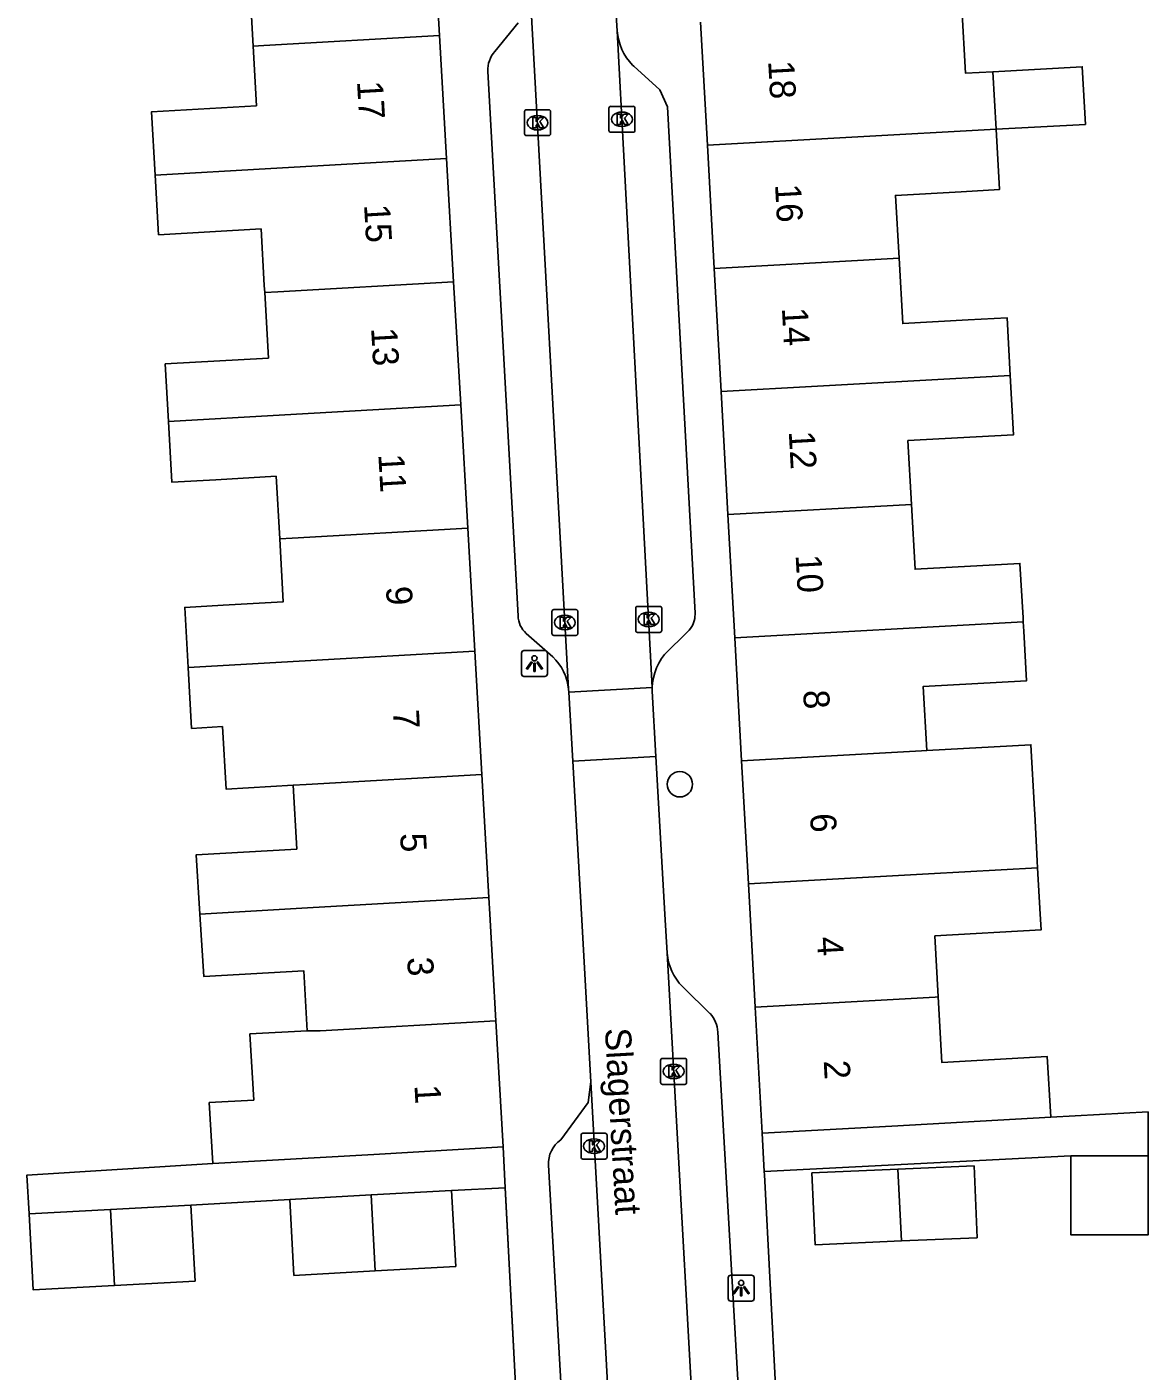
# Model space of a CAD drawing. Extents: x 160861 to 161308, y 384024 to 384878.
# Drawn here: x 161040 to 161083.2, y 384732.4 to 384784.2 of the extents above; entities that cross this region are included whole.
import ezdxf

# ---------------------------------------------------------------- set-up
doc = ezdxf.new("R2010")
doc.units = 0
for name, color, linetype in [('IMGEO_Boom', 7, 'Continuous'), ('IMGEO_Kolk', 7, 'Continuous'), ('IMGEO_Lichtpunt', 7, 'Continuous'), ('IMGEO_Muur', 7, 'Continuous'), ('IMGEO_Openbare_ruimte_label', 7, 'Continuous'), ('IMGEO_Pand', 7, 'Continuous'), ('IMGEO_Pand_nummerreeks', 7, 'Continuous'), ('IMGEO_Rijbaan_lokaal_open', 7, 'Continuous'), ('IMGEO_Voetpad_open', 7, 'Continuous')]:
    doc.layers.add(name, color=color, linetype=linetype)

msp = doc.modelspace()

# ---------------------------------------------------------------- linework, layer by layer
at = {"layer": 'IMGEO_Boom'}
msp.add_circle((161065.12, 384755.001), 0.489, dxfattribs=at)
at = {"layer": 'IMGEO_Kolk'}
for p, q in [((161059.133, 384780.08), (161059.133, 384780.932)), ((161059.208, 384781.006), (161060.06, 384781.006)), ((161059.621, 384780.786), (161059.646, 384780.786)), ((161060.134, 384780.932), (161060.134, 384780.08)), ((161062.387, 384780.21), (161062.387, 384781.062)), ((161062.462, 384781.136), (161063.314, 384781.136)), ((161062.875, 384780.916), (161062.9, 384780.916)), ((161063.388, 384781.062), (161063.388, 384780.21)), ((161059.644, 384780.226), (161059.619, 384780.226)), ((161062.898, 384780.356), (161062.873, 384780.356)), ((161060.06, 384780.006), (161059.208, 384780.006)), ((161063.314, 384780.136), (161062.462, 384780.136)), ((161060.187, 384760.812), (161060.187, 384761.664)), ((161060.262, 384761.738), (161061.114, 384761.738)), ((161060.675, 384761.518), (161060.7, 384761.518)), ((161061.188, 384761.664), (161061.188, 384760.812)), ((161063.417, 384760.932), (161063.417, 384761.784)), ((161063.492, 384761.858), (161064.344, 384761.858)), ((161063.905, 384761.638), (161063.93, 384761.638)), ((161064.418, 384761.784), (161064.418, 384760.932)), ((161063.928, 384761.078), (161063.903, 384761.078)), ((161061.114, 384760.738), (161060.262, 384760.738)), ((161060.698, 384760.958), (161060.673, 384760.958)), ((161064.344, 384760.858), (161063.492, 384760.858)), ((161064.453, 384744.433), (161065.305, 384744.433)), ((161064.378, 384743.507), (161064.378, 384744.359)), ((161064.866, 384744.213), (161064.891, 384744.213)), ((161065.379, 384744.359), (161065.379, 384743.507)), ((161065.305, 384743.433), (161064.453, 384743.433)), ((161064.889, 384743.653), (161064.864, 384743.653)), ((161061.31, 384740.624), (161061.31, 384741.476)), ((161061.385, 384741.55), (161062.237, 384741.55)), ((161061.798, 384741.33), (161061.823, 384741.33)), ((161062.311, 384741.476), (161062.311, 384740.624)), ((161062.237, 384740.55), (161061.385, 384740.55)), ((161061.821, 384740.77), (161061.796, 384740.77))]:
    msp.add_line(p, q, dxfattribs=at)
for points in [[(161059.133, 384780.08), (161059.133, 384780.932)], [(161059.208, 384781.006), (161060.06, 384781.006)], [(161059.454, 384780.706), (161059.577, 384780.706), (161059.577, 384780.555), (161059.707, 384780.706), (161059.871, 384780.706), (161059.725, 384780.555), (161059.878, 384780.306), (161059.726, 384780.306), (161059.641, 384780.47), (161059.577, 384780.403), (161059.577, 384780.306), (161059.454, 384780.306), (161059.454, 384780.706)], [(161060.134, 384780.932), (161060.134, 384780.08)], [(161062.387, 384780.21), (161062.387, 384781.062)], [(161062.462, 384781.136), (161063.314, 384781.136)], [(161062.708, 384780.836), (161062.831, 384780.836), (161062.831, 384780.685), (161062.961, 384780.836), (161063.125, 384780.836), (161062.979, 384780.685), (161063.132, 384780.436), (161062.98, 384780.436), (161062.895, 384780.6), (161062.831, 384780.533), (161062.831, 384780.436), (161062.708, 384780.436), (161062.708, 384780.836)], [(161063.388, 384781.062), (161063.388, 384780.21)], [(161060.06, 384780.006), (161059.208, 384780.006)], [(161063.314, 384780.136), (161062.462, 384780.136)], [(161060.187, 384760.812), (161060.187, 384761.664)], [(161060.262, 384761.738), (161061.114, 384761.738)], [(161061.188, 384761.664), (161061.188, 384760.812)], [(161063.417, 384760.932), (161063.417, 384761.784)], [(161063.492, 384761.858), (161064.344, 384761.858)], [(161063.738, 384761.558), (161063.861, 384761.558), (161063.861, 384761.407), (161063.991, 384761.558), (161064.155, 384761.558), (161064.009, 384761.407), (161064.162, 384761.158), (161064.01, 384761.158), (161063.925, 384761.322), (161063.861, 384761.255), (161063.861, 384761.158), (161063.738, 384761.158), (161063.738, 384761.558)], [(161064.418, 384761.784), (161064.418, 384760.932)], [(161060.508, 384761.438), (161060.631, 384761.438), (161060.631, 384761.287), (161060.761, 384761.438), (161060.925, 384761.438), (161060.779, 384761.287), (161060.932, 384761.038), (161060.78, 384761.038), (161060.695, 384761.202), (161060.631, 384761.135), (161060.631, 384761.038), (161060.508, 384761.038), (161060.508, 384761.438)], [(161061.114, 384760.738), (161060.262, 384760.738)], [(161064.344, 384760.858), (161063.492, 384760.858)], [(161064.453, 384744.433), (161065.305, 384744.433)], [(161064.378, 384743.507), (161064.378, 384744.359)], [(161064.699, 384744.133), (161064.822, 384744.133), (161064.822, 384743.982), (161064.952, 384744.133), (161065.116, 384744.133), (161064.97, 384743.982), (161065.123, 384743.733), (161064.971, 384743.733), (161064.886, 384743.897), (161064.822, 384743.83), (161064.822, 384743.733), (161064.699, 384743.733), (161064.699, 384744.133)], [(161065.379, 384744.359), (161065.379, 384743.507)], [(161065.305, 384743.433), (161064.453, 384743.433)], [(161061.31, 384740.624), (161061.31, 384741.476)], [(161061.385, 384741.55), (161062.237, 384741.55)], [(161062.311, 384741.476), (161062.311, 384740.624)], [(161061.631, 384741.25), (161061.754, 384741.25), (161061.754, 384741.099), (161061.884, 384741.25), (161062.048, 384741.25), (161061.902, 384741.099), (161062.055, 384740.85), (161061.903, 384740.85), (161061.818, 384741.014), (161061.754, 384740.947), (161061.754, 384740.85), (161061.631, 384740.85), (161061.631, 384741.25)], [(161062.237, 384740.55), (161061.385, 384740.55)]]:
    msp.add_lwpolyline(points, dxfattribs=at)
for centre, start, end in [((161059.21, 384780.93), 91.552, 178.448), ((161059.21, 384780.93), 91.552, 178.448), ((161060.058, 384780.93), 1.552, 88.448), ((161060.058, 384780.93), 1.552, 88.448), ((161062.464, 384781.06), 91.552, 178.448), ((161062.464, 384781.06), 91.552, 178.448), ((161063.312, 384781.06), 1.552, 88.448), ((161063.312, 384781.06), 1.552, 88.448), ((161062.464, 384780.212), 181.552, 268.448), ((161062.464, 384780.212), 181.552, 268.448), ((161063.312, 384780.212), 271.552, 358.448), ((161063.312, 384780.212), 271.552, 358.448), ((161059.21, 384780.082), 181.552, 268.448), ((161059.21, 384780.082), 181.552, 268.448), ((161060.058, 384780.082), 271.552, 358.448), ((161060.058, 384780.082), 271.552, 358.448), ((161060.264, 384761.662), 91.552, 178.448), ((161060.264, 384761.662), 91.552, 178.448), ((161061.112, 384761.662), 1.552, 88.448), ((161061.112, 384761.662), 1.552, 88.448), ((161063.494, 384761.782), 91.552, 178.448), ((161063.494, 384761.782), 91.552, 178.448), ((161064.342, 384761.782), 1.552, 88.448), ((161064.342, 384761.782), 1.552, 88.448), ((161060.264, 384760.814), 181.552, 268.448), ((161060.264, 384760.814), 181.552, 268.448), ((161061.112, 384760.814), 271.552, 358.448), ((161061.112, 384760.814), 271.552, 358.448), ((161063.494, 384760.934), 181.552, 268.448), ((161063.494, 384760.934), 181.552, 268.448), ((161064.342, 384760.934), 271.552, 358.448), ((161064.342, 384760.934), 271.552, 358.448), ((161064.455, 384744.357), 91.552, 178.448), ((161064.455, 384744.357), 91.552, 178.448), ((161065.303, 384744.357), 1.552, 88.448), ((161065.303, 384744.357), 1.552, 88.448), ((161064.455, 384743.509), 181.552, 268.448), ((161064.455, 384743.509), 181.552, 268.448), ((161065.303, 384743.509), 271.552, 358.448), ((161065.303, 384743.509), 271.552, 358.448), ((161061.387, 384741.474), 91.552, 178.448), ((161061.387, 384741.474), 91.552, 178.448), ((161062.235, 384741.474), 1.552, 88.448), ((161062.235, 384741.474), 1.552, 88.448), ((161061.387, 384740.626), 181.552, 268.448), ((161061.387, 384740.626), 181.552, 268.448), ((161062.235, 384740.626), 271.552, 358.448), ((161062.235, 384740.626), 271.552, 358.448)]:
    msp.add_arc(centre, 0.0765, start, end, dxfattribs=at)
for centre, major_axis, ratio, start_param, end_param in [((161059.62, 384780.506), (-0.387, 0.002), 0.722429, 4.712389, 7.853982), ((161059.645, 384780.506), (-0.39, 0.002), 0.717154, 1.570796, 4.712389), ((161062.874, 384780.636), (-0.387, 0.002), 0.722429, 4.712389, 7.853982), ((161062.899, 384780.636), (-0.39, 0.002), 0.717154, 1.570796, 4.712389), ((161060.674, 384761.238), (-0.387, 0.002), 0.722429, 4.712389, 7.853982), ((161060.699, 384761.238), (-0.39, 0.002), 0.717154, 1.570796, 4.712389), ((161063.904, 384761.358), (-0.387, 0.002), 0.722429, 4.712389, 7.853982), ((161063.929, 384761.358), (-0.39, 0.002), 0.717154, 1.570796, 4.712389), ((161064.865, 384743.933), (-0.387, 0.002), 0.722429, 4.712389, 7.853982), ((161064.89, 384743.933), (-0.39, 0.002), 0.717154, 1.570796, 4.712389), ((161061.797, 384741.05), (-0.387, 0.002), 0.722429, 4.712389, 7.853982), ((161061.822, 384741.05), (-0.39, 0.002), 0.717154, 1.570796, 4.712389)]:
    msp.add_ellipse(centre, major_axis=major_axis, ratio=ratio, start_param=start_param, end_param=end_param, dxfattribs=at)
at = {"layer": 'IMGEO_Lichtpunt'}
for p, q in [((161059.016, 384760.06), (161059.016, 384759.253)), ((161059.016, 384760.06), (161059.016, 384759.253)), ((161059.918, 384760.155), (161059.11, 384760.155)), ((161059.918, 384760.155), (161059.11, 384760.155)), ((161060.012, 384759.253), (161060.012, 384760.06)), ((161060.012, 384759.253), (161060.012, 384760.06)), ((161059.11, 384759.159), (161059.918, 384759.159)), ((161059.11, 384759.159), (161059.918, 384759.159)), ((161066.984, 384735.981), (161066.984, 384735.174)), ((161066.984, 384735.981), (161066.984, 384735.174)), ((161067.886, 384736.076), (161067.078, 384736.076)), ((161067.886, 384736.076), (161067.078, 384736.076)), ((161067.98, 384735.174), (161067.98, 384735.981)), ((161067.98, 384735.174), (161067.98, 384735.981)), ((161067.078, 384735.08), (161067.886, 384735.08)), ((161067.078, 384735.08), (161067.886, 384735.08))]:
    msp.add_line(p, q, dxfattribs=at)
for points in [[(161059.39, 384759.724), (161059.429, 384759.696), (161059.241, 384759.434), (161059.203, 384759.461), (161059.39, 384759.724)], [(161059.492, 384759.676), (161059.539, 384759.676), (161059.539, 384759.354), (161059.492, 384759.354), (161059.492, 384759.676)], [(161059.602, 384759.696), (161059.64, 384759.723), (161059.827, 384759.461), (161059.788, 384759.433), (161059.602, 384759.696)], [(161067.358, 384735.645), (161067.397, 384735.617), (161067.209, 384735.355), (161067.171, 384735.382), (161067.358, 384735.645)], [(161067.57, 384735.617), (161067.608, 384735.644), (161067.795, 384735.382), (161067.756, 384735.354), (161067.57, 384735.617)], [(161067.46, 384735.597), (161067.507, 384735.597), (161067.507, 384735.275), (161067.46, 384735.275), (161067.46, 384735.597)]]:
    msp.add_lwpolyline(points, dxfattribs=at)
for centre in [(161059.515, 384759.858), (161067.483, 384735.779)]:
    msp.add_circle(centre, 0.0994, dxfattribs=at)
for centre, start, end in [((161059.11, 384760.06), 90, 180), ((161059.11, 384760.06), 90, 180), ((161059.918, 384760.06), 0, 90), ((161059.918, 384760.06), 0, 90), ((161059.11, 384759.253), 180, 270), ((161059.11, 384759.253), 180, 270), ((161059.918, 384759.253), 270, 0), ((161059.918, 384759.253), 270, 360), ((161067.078, 384735.981), 90, 180), ((161067.078, 384735.981), 90, 180), ((161067.886, 384735.981), 0, 90), ((161067.886, 384735.981), 0, 90), ((161067.078, 384735.174), 180, 270), ((161067.078, 384735.174), 180, 270), ((161067.886, 384735.174), 270, 0), ((161067.886, 384735.174), 270, 360)]:
    msp.add_arc(centre, 0.0946, start, end, dxfattribs=at)
at = {"layer": 'IMGEO_Muur'}
for points in [[(161068.378, 384739.94), (161068.814, 384731.561)], [(161058.391, 384739.453), (161058.841, 384730.88)]]:
    msp.add_lwpolyline(points, dxfattribs=at)
at = {"layer": 'IMGEO_Pand'}
for points in [[(161055.585, 384788.618), (161055.857, 384783.87)], [(161048.67, 384783.459), (161048.538, 384785.766), (161044.542, 384785.537), (161044.402, 384787.978)], [(161073.083, 384784.777), (161075.991, 384784.939), (161076.132, 384782.412), (161077.185, 384782.47)], [(161066.178, 384779.633), (161065.914, 384784.379)], [(161055.857, 384783.87), (161049.083, 384783.483), (161048.67, 384783.459)], [(161055.857, 384783.87), (161056.129, 384779.122)], [(161044.896, 384778.48), (161044.756, 384780.929), (161048.801, 384781.161), (161048.67, 384783.459)], [(161077.309, 384780.251), (161080.753, 384780.441), (161080.631, 384782.66), (161077.185, 384782.47)], [(161077.185, 384782.47), (161077.309, 384780.251)], [(161077.309, 384780.251), (161066.178, 384779.633)], [(161077.309, 384780.251), (161077.438, 384777.926), (161075.957, 384777.843), (161073.43, 384777.701), (161073.566, 384775.283)], [(161066.442, 384774.887), (161066.178, 384779.633)], [(161056.129, 384779.122), (161049.355, 384778.735), (161044.896, 384778.48)], [(161056.129, 384779.122), (161056.4, 384774.374)], [(161049.117, 384773.958), (161049.102, 384774.223), (161048.976, 384776.411), (161045.027, 384776.185), (161044.896, 384778.48)], [(161066.442, 384774.887), (161073.566, 384775.283)], [(161073.566, 384775.283), (161073.707, 384772.761), (161076.232, 384772.901), (161077.732, 384772.984), (161077.856, 384770.761)], [(161066.705, 384770.141), (161066.442, 384774.887)], [(161045.408, 384768.982), (161045.281, 384771.204), (161049.263, 384771.434), (161049.117, 384773.958)], [(161056.4, 384774.374), (161049.627, 384773.987), (161049.117, 384773.958)], [(161056.4, 384774.374), (161056.672, 384769.627)], [(161066.705, 384770.141), (161077.856, 384770.761)], [(161077.856, 384770.761), (161077.983, 384768.478), (161073.91, 384768.252), (161074.047, 384765.789)], [(161066.969, 384765.395), (161066.705, 384770.141)], [(161045.408, 384768.982), (161049.899, 384769.239), (161056.672, 384769.627)], [(161056.672, 384769.627), (161056.944, 384764.879)], [(161049.695, 384764.464), (161049.558, 384766.875), (161047.24, 384766.743), (161045.541, 384766.646), (161045.408, 384768.982)], [(161074.047, 384765.789), (161066.969, 384765.395)], [(161074.047, 384765.789), (161074.186, 384763.289), (161078.225, 384763.513), (161078.345, 384761.413), (161078.353, 384761.267)], [(161067.233, 384760.649), (161066.969, 384765.395)], [(161049.695, 384764.464), (161050.171, 384764.491), (161056.944, 384764.879)], [(161056.944, 384764.879), (161057.215, 384760.131)], [(161046.168, 384759.498), (161046.035, 384761.818), (161047.517, 384761.903), (161049.834, 384762.036), (161049.695, 384764.464)], [(161067.233, 384760.649), (161078.353, 384761.267)], [(161078.353, 384761.267), (161078.374, 384760.898), (161078.482, 384758.995), (161074.501, 384758.773), (161074.639, 384756.3)], [(161067.497, 384755.903), (161067.233, 384760.649)], [(161057.215, 384760.131), (161050.443, 384759.743), (161046.168, 384759.498)], [(161057.215, 384760.131), (161057.487, 384755.383)], [(161050.212, 384754.966), (161047.627, 384754.817), (161047.489, 384757.224), (161046.302, 384757.156), (161046.168, 384759.498)], [(161078.91, 384751.777), (161078.896, 384752.04), (161078.881, 384752.303), (161078.8, 384753.863), (161078.791, 384754.027), (161078.652, 384756.524), (161074.639, 384756.3)], [(161074.639, 384756.3), (161074.434, 384756.289), (161067.497, 384755.903)], [(161067.761, 384751.157), (161067.497, 384755.903)], [(161050.212, 384754.966), (161050.715, 384754.995), (161057.487, 384755.383)], [(161057.487, 384755.383), (161057.759, 384750.635)], [(161046.617, 384749.998), (161046.475, 384752.278), (161050.353, 384752.5), (161050.212, 384754.966)], [(161067.761, 384751.157), (161074.698, 384751.543), (161078.91, 384751.777)], [(161078.91, 384751.777), (161079.01, 384750), (161079.044, 384749.384), (161074.947, 384749.156), (161075.078, 384746.803)], [(161068.025, 384746.411), (161067.825, 384750), (161067.761, 384751.157)], [(161057.759, 384750.635), (161050.987, 384750.248), (161046.617, 384749.998)], [(161057.759, 384750.635), (161057.795, 384750), (161058.03, 384745.887)], [(161050.758, 384745.501), (161050.625, 384747.814), (161046.767, 384747.593), (161046.617, 384749.998)], [(161075.078, 384746.803), (161074.962, 384746.797), (161068.025, 384746.411)], [(161075.078, 384746.803), (161075.218, 384744.275), (161079.282, 384744.501), (161079.412, 384742.164)], [(161068.295, 384741.546), (161068.025, 384746.411)], [(161047.112, 384740.379), (161046.978, 384742.729), (161048.693, 384742.827), (161048.547, 384745.375), (161050.758, 384745.501)], [(161050.758, 384745.501), (161051.259, 384745.5), (161058.03, 384745.887)], [(161058.03, 384745.887), (161058.309, 384741.02)], [(161079.412, 384742.164), (161073.288, 384741.824), (161068.295, 384741.546)], [(161058.309, 384741.02), (161053.318, 384740.734), (161047.112, 384740.379)], [(161073.521, 384740.164), (161076.457, 384740.291), (161076.577, 384737.522), (161073.664, 384737.396)], [(161083.167, 384740.682), (161083.167, 384737.63), (161080.192, 384737.63), (161080.192, 384740.682)], [(161080.192, 384740.682), (161083.167, 384740.682)], [(161073.664, 384737.396), (161070.332, 384737.251), (161070.212, 384740.02), (161073.521, 384740.164)], [(161073.521, 384740.164), (161073.664, 384737.396)], [(161053.216, 384739.17), (161056.321, 384739.34)], [(161056.321, 384739.34), (161056.481, 384736.412), (161053.379, 384736.242)], [(161043.168, 384738.609), (161046.273, 384738.779)], [(161046.273, 384738.779), (161046.433, 384735.851), (161043.331, 384735.681)], [(161050.081, 384738.998), (161053.216, 384739.17)], [(161053.379, 384736.242), (161050.241, 384736.07), (161050.081, 384738.998)], [(161053.379, 384736.242), (161053.216, 384739.17)], [(161040.033, 384738.437), (161043.168, 384738.609)], [(161043.331, 384735.681), (161040.193, 384735.509), (161040.033, 384738.437)], [(161043.331, 384735.681), (161043.168, 384738.609)]]:
    msp.add_lwpolyline(points, dxfattribs=at)
at = {"layer": 'IMGEO_Rijbaan_lokaal_open'}
for points in [[(161062.512, 384787.086), (161062.707, 384784.049)], [(161060.831, 384758.662), (161059.355, 384785.558)], [(161062.707, 384784.049), (161064.049, 384758.727)], [(161060.837, 384758.55), (161060.831, 384758.662)], [(161064.049, 384758.727), (161060.837, 384758.55)], [(161060.988, 384755.894), (161060.837, 384758.55)], [(161064.049, 384758.727), (161064.047, 384758.585), (161064.192, 384756.072)], [(161064.192, 384756.072), (161060.988, 384755.894)], [(161061.691, 384743.529), (161061.323, 384750), (161060.988, 384755.894)], [(161064.192, 384756.072), (161064.543, 384750), (161064.63, 384748.494)], [(161064.63, 384748.494), (161065.98, 384724.229)], [(161062.749, 384724.24), (161061.691, 384743.529)]]:
    msp.add_lwpolyline(points, dxfattribs=at)
at = {"layer": 'IMGEO_Voetpad_open'}
for points in [[(161057.984, 384783.254), (161058.891, 384784.349)], [(161062.707, 384784.049), (161062.726, 384783.865), (161062.762, 384783.683), (161062.814, 384783.505), (161062.881, 384783.333), (161062.964, 384783.167), (161063.061, 384783.009), (161063.172, 384782.861), (161063.296, 384782.723), (161063.339, 384782.68), (161064.342, 384781.773), (161064.644, 384781.111), (161065.704, 384761.592), (161065.705, 384761.551), (161065.702, 384761.469), (161065.692, 384761.388), (161065.674, 384761.307), (161065.649, 384761.229), (161065.618, 384761.153), (161065.58, 384761.08), (161065.535, 384761.011), (161065.484, 384760.946), (161065.428, 384760.886), (161064.527, 384760.01), (161064.41, 384759.847), (161064.308, 384759.673), (161064.222, 384759.492), (161064.153, 384759.303), (161064.1, 384759.109), (161064.065, 384758.911), (161064.049, 384758.727)], [(161058.885, 384761.496), (161057.72, 384782.485)], [(161060.219, 384759.918), (161059.195, 384760.818)], [(161064.63, 384748.494), (161064.65, 384748.315), (161064.687, 384748.138), (161064.739, 384747.965), (161064.806, 384747.798), (161064.888, 384747.637), (161064.984, 384747.484), (161065.093, 384747.34), (161065.215, 384747.207), (161065.276, 384747.148), (161066.271, 384746.171), (161066.283, 384746.159), (161066.347, 384746.085), (161066.405, 384746.005), (161066.455, 384745.921), (161066.497, 384745.832), (161066.532, 384745.74), (161066.558, 384745.645), (161066.575, 384745.549), (161066.584, 384745.451), (161067.557, 384728.452)], [(161060.529, 384741.299), (161061.583, 384742.73), (161061.691, 384743.529)], [(161083.167, 384740.682), (161083.167, 384742.372), (161079.412, 384742.164)], [(161068.371, 384740.071), (161068.295, 384741.546)], [(161058.309, 384741.02), (161058.391, 384739.448)], [(161047.112, 384740.379), (161039.951, 384739.934), (161040.033, 384738.437)], [(161060.782, 384727.319), (161060.736, 384728.324), (161060.055, 384740.313)], [(161068.371, 384740.071), (161080.192, 384740.682)], [(161068.814, 384731.561), (161068.378, 384739.94), (161068.371, 384740.071)], [(161056.321, 384739.34), (161058.391, 384739.448)], [(161058.391, 384739.448), (161058.841, 384730.88)], [(161046.273, 384738.779), (161050.081, 384738.998)]]:
    msp.add_lwpolyline(points, dxfattribs=at)
for centre, radius, start, end in [((161058.785, 384782.549), 1.067, 138.6546, 183.4504), ((161059.802, 384761.505), 0.917, 180.5798, 228.5626), ((161058.823, 384758.461), 2.018, 5.7244, 46.232), ((161061.186, 384740.376), 1.132, 125.4381, 183.2119)]:
    msp.add_arc(centre, radius, start, end, dxfattribs=at)

# ---------------------------------------------------------------- texts
at = {"layer": 'IMGEO_Openbare_ruimte_label'}
msp.add_text('Slagerstraat', height=1, rotation=273.2689, dxfattribs=at).set_placement((161062.229, 384745.586))
at = {"layer": 'IMGEO_Pand_nummerreeks'}
for s, rotation, p in [('18', 273.1797, (161068.522, 384782.877)), ('17', 273.2747, (161052.674, 384782.095)), ('16', 273.1797, (161068.786, 384778.12)), ('15', 273.2771, (161052.946, 384777.339)), ('14', 273.1797, (161069.051, 384773.36)), ('13', 273.2771, (161053.218, 384772.583)), ('12', 273.1815, (161069.315, 384768.603)), ('11', 273.2771, (161053.496, 384767.714)), ('10', 273.1797, (161069.58, 384763.837)), ('9', 273.2771, (161053.788, 384762.612)), ('8', 273.1797, (161069.87, 384758.616)), ('7', 273.2771, (161054.06, 384757.856)), ('6', 273.1797, (161070.134, 384753.86)), ('5', 273.2747, (161054.332, 384753.1)), ('4', 273.1815, (161070.399, 384749.1)), ('3', 273.2759, (161054.606, 384748.319)), ('2', 273.1815, (161070.663, 384744.342)), ('1', 273.2759, (161054.888, 384743.397))]:
    msp.add_text(s, height=1, rotation=rotation, dxfattribs=at).set_placement(p)

doc.saveas('drawing.dxf')
